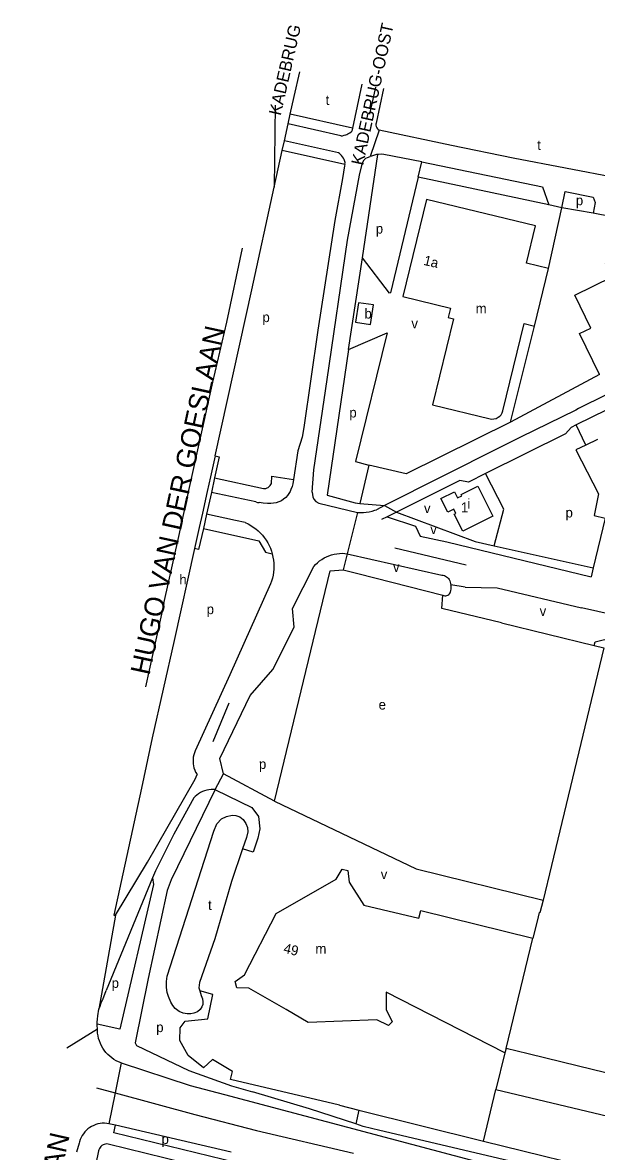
# Model space of a CAD drawing. Extents: x 162804 to 165059, y 381530 to 382901.
# Drawn here: x 163020.7 to 163254, y 382442.3 to 382900.9 of the extents above; entities that cross this region are included whole.
import ezdxf

# ---------------------------------------------------------------- set-up
doc = ezdxf.new("R2010")
doc.units = 0
for name, color, linetype in [('BLT_Basislijn', 7, 'Continuous'), ('BLT_Bebouwing', 7, 'Continuous'), ('BLT_Centroide', 7, 'Continuous'), ('BLT_Huisnummer', 7, 'Continuous'), ('BLT_Onderverdeling_panden', 7, 'Continuous'), ('BLT_Straatnaam', 7, 'Continuous'), ('BLT_Straatnaam_hoofdweg', 7, 'Continuous'), ('BLT_Vlakafsluiter', 7, 'Continuous')]:
    doc.layers.add(name, color=color, linetype=linetype)

msp = doc.modelspace()

# ---------------------------------------------------------------- linework, layer by layer
at = {"layer": 'BLT_Basislijn'}
for p, q in [((163131.06, 382870.79), (163133.35, 382880.87)), ((163158.64, 382875.8), (163154.76, 382858.01)), ((163164.16, 382874.7), (163161.76, 382863.69)), ((163167.47, 382874.04), (163164.41, 382860.02)), ((163129.49, 382863.62), (163131.06, 382870.79)), ((163127.14, 382852.84), (163128.64, 382859.71)), ((163128.64, 382859.71), (163129.49, 382863.62)), ((163154.76, 382858.01), (163154.5, 382856.8)), ((163195.06, 382850.97), (163165.62, 382857.21)), ((163126.28, 382848.93), (163127.14, 382852.84)), ((163123.04, 382834.08), (163126.28, 382848.93)), ((163181.57, 382838.06), (163183.05, 382844.29)), ((163234.54, 382800.98), (163240, 382825.68)), ((163153.25, 382768.15), (163158.84, 382805.26)), ((163219.01, 382738.59), (163228.81, 382777.5)), ((163299.49, 382763.84), (163245.82, 382737.43)), ((163255.22, 382757.98), (163219.01, 382738.59)), ((163249.72, 382729.24), (163245.82, 382737.43)), ((163214.74, 382728.24), (163167.81, 382704.66)), ((163098.97, 382724.93), (163097.07, 382716.36)), ((163097.07, 382716.36), (163095.75, 382710.42)), ((163098.78, 382715.98), (163097.47, 382710.05)), ((163098.78, 382715.98), (163118.59, 382711.58)), ((163121.92, 382713.69), (163122.04, 382716.59)), ((163122.04, 382716.59), (163130.81, 382715.3)), ((163095.75, 382710.42), (163093.8, 382701.6)), ((163097.47, 382710.05), (163095.52, 382701.22)), ((163115.46, 382706.15), (163097.47, 382710.05)), ((163157.82, 382705.56), (163167.81, 382704.66)), ((163167.81, 382704.66), (163164.52, 382703)), ((163093.8, 382701.6), (163092.51, 382695.79)), ((163095.52, 382701.22), (163094.24, 382695.41)), ((163156.91, 382701.93), (163152.71, 382685.13)), ((163168.89, 382700.14), (163166.62, 382699.01)), ((163172.66, 382702.02), (163168.89, 382700.14)), ((163092.51, 382695.79), (163090.61, 382687.21)), ((163090.61, 382687.21), (163082.34, 382649.92)), ((163172.04, 382687.5), (163201.03, 382680.57)), ((163212.49, 382688.33), (163252.69, 382679.34)), ((163152.71, 382685.13), (163191.18, 382676.38)), ((163252.69, 382679.34), (163251.83, 382675.68)), ((163121.51, 382672.9), (163104.93, 382635.89)), ((163194.35, 382674.13), (163194.79, 382672.55)), ((163078.08, 382664.93), (163070.68, 382631.05)), ((163215.41, 382657.03), (163253.08, 382647.9)), ((163253.08, 382647.9), (163257.08, 382646.93)), ((163104.93, 382635.89), (163090.89, 382605.04)), ((163104.57, 382624.4), (163098.01, 382608.72)), ((163098.98, 382589.29), (163102.38, 382595.76)), ((163099.17, 382589.28), (163098.98, 382589.29)), ((163099.17, 382589.28), (163113.86, 382582.1)), ((163073.55, 382553.53), (163054.64, 382507.76)), ((163053.27, 382504.11), (163054.64, 382507.76)), ((163216.75, 382482.33), (163213.07, 382467.42)), ((163102.84, 382465.46), (163245.33, 382427.71)), ((163208.07, 382446.49), (163213.07, 382467.42)), ((163213.07, 382467.42), (163350, 382434.88)), ((163149.58, 382461.08), (163157.34, 382459.15)), ((163157.34, 382459.15), (163156.24, 382453.48)), ((163157.34, 382459.15), (163208.07, 382446.49)), ((163058.49, 382452.93), (163055.79, 382453.57)), ((163057.73, 382449.9), (163058.49, 382452.93)), ((163105.48, 382442), (163058.49, 382452.93)), ((163113.31, 382436.31), (163057.73, 382449.9)), ((163051.6, 382442.55), (163036.49, 382372.02)), ((163043.68, 382445.63), (163042.61, 382441.97)), ((163115.9, 382430.53), (163055.43, 382445.32)), ((163208.07, 382446.49), (163350, 382411.77))]:
    msp.add_line(p, q, dxfattribs=at)
for points in [[(163150.12, 382854.94), (163128.64, 382859.71)], [(163154.76, 382858.01), (163129.49, 382863.62)], [(163164.41, 382860.02), (163164.37, 382859.62), (163164.37, 382859.16), (163164.47, 382858.65), (163164.69, 382858.12), (163164.94, 382857.77), (163165.23, 382857.5), (163165.62, 382857.21)], [(163150.12, 382854.94), (163150.8, 382854.93), (163151.41, 382855.09), (163152.08, 382855.28), (163152.55, 382855.46), (163152.95, 382855.64), (163153.69, 382856.11), (163154.29, 382856.51), (163154.5, 382856.8)], [(163149.07, 382847.94), (163127.14, 382852.84)], [(163262.7, 382837.7), (163220.15, 382845.79), (163195.06, 382850.97)], [(163151.69, 382843.25), (163126.28, 382848.93)], [(163138.38, 382710.09), (163139.04, 382719.2), (163144.49, 382755.86), (163152.81, 382812.54), (163157.67, 382838.95), (163158.87, 382843.86), (163159.61, 382845.11), (163160.28, 382845.75), (163160.93, 382846.09), (163162.05, 382846.43)], [(163151.68, 382843.24), (163151.8, 382844.07), (163151.74, 382844.42), (163151.57, 382844.89), (163151.39, 382845.22), (163151.11, 382845.76), (163150.78, 382846.28), (163150.31, 382846.88), (163149.79, 382847.48), (163149.52, 382847.71), (163149.07, 382847.94)], [(163158.84, 382805.26), (163165.1, 382847.3)], [(163165.1, 382847.3), (163164.58, 382847.23), (163163.4, 382846.94), (163162.6, 382846.66), (163162.05, 382846.43)], [(163183.05, 382844.29), (163167.53, 382847.36), (163166.55, 382847.41), (163165.44, 382847.35), (163165.1, 382847.3)], [(163151.68, 382843.24), (163151.64, 382842.74), (163150.73, 382837.51), (163147.6, 382820.47), (163140.79, 382775.98), (163134.99, 382736.38), (163134.35, 382732.42), (163132.58, 382726.92), (163130.81, 382715.3)], [(163183.05, 382844.29), (163232.1, 382834.21), (163234.59, 382826.79)], [(163181.57, 382838.06), (163170.28, 382791.11), (163169.86, 382790.92), (163158.84, 382805.26)], [(163234.59, 382826.79), (163181.57, 382838.06)], [(163098.97, 382724.93), (163113.91, 382792.3), (163123.04, 382834.08)], [(163240, 382825.68), (163241.32, 382832.3), (163252.7, 382829.96), (163253.56, 382827.74), (163252.7, 382823.52)], [(163240, 382825.68), (163234.59, 382826.79)], [(163252.7, 382823.52), (163240, 382825.68)], [(163260.28, 382821.96), (163252.7, 382823.52)], [(163098.1, 382754.82), (163103.69, 382779.15), (163110.05, 382809.31)], [(163342.88, 382788.54), (163334.37, 382786.16), (163324.71, 382782.9), (163300, 382770.11), (163280.94, 382760.98), (163246.71, 382744.11), (163245.68, 382743.43), (163223.18, 382732.48), (163214.74, 382728.24)], [(163153.25, 382768.15), (163168.88, 382774.85), (163156.04, 382722.53), (163161.49, 382721.16)], [(163153.25, 382768.15), (163144.56, 382708.96), (163155.87, 382705.74), (163157.82, 382705.56)], [(163088.58, 382711.97), (163098.1, 382754.82)], [(163219.01, 382738.59), (163176.6, 382717.59), (163161.49, 382721.16)], [(163245.82, 382737.43), (163243.69, 382736.38), (163241.47, 382733.8), (163208.95, 382717.76)], [(163254.47, 382731.57), (163249.72, 382729.24)], [(163249.72, 382729.24), (163245.69, 382727.26), (163254.86, 382709.41), (163253.04, 382700.65), (163257.5, 382699.61), (163252.69, 382679.34)], [(163098.97, 382724.93), (163100.68, 382724.55), (163098.78, 382715.98)], [(163161.49, 382721.16), (163157.82, 382705.56)], [(163208.95, 382717.76), (163201.99, 382714.15), (163198.52, 382714.88), (163172.66, 382702.02)], [(163212.49, 382688.33), (163216.34, 382703.16), (163208.95, 382717.76)], [(163130.81, 382715.3), (163130.54, 382713.58), (163130.26, 382712.47), (163129.8, 382711.16), (163129.48, 382710.42), (163128.95, 382709.53), (163128.36, 382708.74), (163127.69, 382707.98), (163126.82, 382707.25), (163125.9, 382706.65), (163124.86, 382706.17), (163123.8, 382705.84), (163122.68, 382705.61), (163121.57, 382705.5), (163120.21, 382705.48), (163118.51, 382705.68), (163116.94, 382705.89)], [(163118.59, 382711.58), (163119.11, 382711.59), (163119.62, 382711.68), (163120.11, 382711.85), (163120.57, 382712.09), (163120.99, 382712.4), (163121.36, 382712.77), (163121.66, 382713.19), (163121.92, 382713.69)], [(163078.08, 382664.93), (163084.25, 382692.16), (163088.58, 382711.97)], [(163138.38, 382710.09), (163138.64, 382708.3), (163139.1, 382707.22), (163139.9, 382706.36), (163141.09, 382705.65), (163156.91, 382701.93)], [(163115.46, 382706.15), (163116.24, 382705.97), (163116.94, 382705.89)], [(163111.24, 382697.77), (163107.3, 382698.6), (163095.52, 382701.22)], [(163156.91, 382701.93), (163158.09, 382701.88), (163159.27, 382701.9), (163160.45, 382702), (163161.62, 382702.18), (163162.77, 382702.44), (163163.9, 382702.78), (163164.52, 382703)], [(163168.89, 382700.14), (163180.47, 382696.27), (163182.3, 382692.26), (163193.24, 382689.89), (163251.83, 382675.68)], [(163172.66, 382702.02), (163204.72, 382690.07), (163212.49, 382688.33)], [(163094.24, 382695.41), (163092.16, 382686.86), (163090.61, 382687.21)], [(163094.24, 382695.41), (163116.78, 382690.4), (163119.41, 382685.76), (163122.2, 382685.07)], [(163111.24, 382697.77), (163112.36, 382697.24), (163113.45, 382696.63), (163114.49, 382695.96), (163115.5, 382695.22), (163116.45, 382694.42), (163117.35, 382693.56), (163118.19, 382692.64), (163118.97, 382691.67), (163119.68, 382690.65), (163120.34, 382689.59), (163120.92, 382688.49), (163121.42, 382687.36), (163121.86, 382686.19), (163122.2, 382685.07)], [(163139.08, 382679.93), (163139.81, 382680.74), (163140.6, 382681.49), (163141.44, 382682.19), (163142.33, 382682.83), (163143.26, 382683.4), (163144.23, 382683.89), (163145.24, 382684.32), (163146.27, 382684.67), (163147.33, 382684.94), (163148.4, 382685.14), (163149.49, 382685.26), (163150.58, 382685.29), (163151.67, 382685.25), (163152.71, 382685.13)], [(163122.2, 382685.07), (163122.5, 382683.79), (163122.7, 382682.56), (163122.83, 382681.32), (163122.87, 382680.08), (163122.83, 382678.83), (163122.72, 382677.59), (163122.52, 382676.36), (163122.25, 382675.15), (163121.9, 382673.96), (163121.51, 382672.9)], [(163152.71, 382685.13), (163151.07, 382678.57)], [(163102.38, 382595.76), (163100.86, 382601.96), (163113.25, 382627.5), (163122.37, 382638.08), (163131.12, 382655.23), (163130.39, 382662.89), (163139.08, 382679.93)], [(163123.14, 382584.58), (163145.77, 382678.15), (163151.07, 382678.57)], [(163151.07, 382678.57), (163157.03, 382677.05)], [(163157.03, 382677.05), (163191.57, 382668.27)], [(163191.18, 382676.38), (163191.69, 382676.35), (163192.19, 382676.24), (163192.67, 382676.05), (163193.11, 382675.79), (163193.51, 382675.47), (163193.85, 382675.09), (163194.12, 382674.66), (163194.35, 382674.13)], [(163194.69, 382669.54), (163194.86, 382670.15), (163194.96, 382670.78), (163194.97, 382671.41), (163194.9, 382672.04), (163194.79, 382672.55)], [(163200.64, 382671.5), (163213.64, 382671.33), (163247.91, 382663.13)], [(163215.41, 382657.03), (163191.12, 382662.93), (163191.57, 382668.27)], [(163191.57, 382668.27), (163191.98, 382668.13), (163192.4, 382668.06), (163192.83, 382668.07), (163193.24, 382668.16), (163193.64, 382668.33), (163193.99, 382668.57), (163194.3, 382668.87), (163194.54, 382669.22), (163194.69, 382669.54)], [(163082.34, 382649.92), (163073.42, 382610.36), (163069.04, 382589.94)], [(163253.08, 382647.9), (163253.44, 382649.38), (163267.8, 382652.86), (163288.01, 382648.03)], [(163090.89, 382605.04), (163090.56, 382604.22), (163090.29, 382603.37), (163090.11, 382602.5), (163090.01, 382601.61), (163089.98, 382600.73), (163090.04, 382599.84), (163090.17, 382598.96), (163090.38, 382598.09), (163090.67, 382597.25), (163091.04, 382596.44), (163091.47, 382595.67), (163091.64, 382595.41)], [(163058.48, 382538.35), (163071.41, 382559.86), (163090.91, 382593.59), (163091.64, 382595.41)], [(163123.14, 382584.58), (163102.38, 382595.76)], [(163069.04, 382589.94), (163057.75, 382538.35), (163058.48, 382538.35)], [(163098.98, 382589.29), (163081.08, 382552.64), (163079.44, 382548.27), (163071.78, 382512.54)], [(163098.98, 382589.29), (163098.26, 382589.35), (163097.35, 382589.34), (163096.45, 382589.24), (163095.56, 382589.08), (163094.68, 382588.83), (163093.84, 382588.5), (163093.02, 382588.11), (163092.24, 382587.64), (163091.51, 382587.11), (163090.82, 382586.51), (163090.33, 382586.01)], [(163090.33, 382586.01), (163082.16, 382571.22), (163074.69, 382556.27), (163073.55, 382553.53)], [(163123.14, 382584.58), (163180.65, 382557.11), (163232.29, 382544.44)], [(163113.86, 382582.1), (163116.57, 382578.36), (163117.21, 382573.31), (163116.3, 382569.58), (163114.44, 382563.9), (163110.13, 382565.26)], [(163093.85, 382504.27), (163094.01, 382503.13), (163093.92, 382501.98), (163093.59, 382501.07), (163092.92, 382499.98), (163091.86, 382499.09), (163090.29, 382498.44), (163089.05, 382498.21), (163087.56, 382498.19), (163085.99, 382498.48), (163084.36, 382499.19), (163082.78, 382500.34), (163081.72, 382501.54), (163080.95, 382502.95), (163079.99, 382505.25), (163079.51, 382506.94), (163079.19, 382508.95), (163079.15, 382511.36), (163079.41, 382513.58), (163098.44, 382572.38), (163099.71, 382575.41), (163101.56, 382577.37), (163103.57, 382578.44), (163105.84, 382578.95), (163107.42, 382578.83), (163108.96, 382578.2), (163110.35, 382577.16), (163111.49, 382575.57), (163112.1, 382573.95), (163112.26, 382572.18), (163111.67, 382569.8), (163110.13, 382565.26)], [(163110.13, 382565.26), (163105.63, 382551.99), (163098.86, 382528.65), (163092.62, 382510.96), (163092.42, 382509.84), (163092.37, 382508.78), (163092.7, 382507.58)], [(163073.55, 382553.53), (163073.88, 382550.7), (163060.21, 382491.97), (163051, 382494.09)], [(163071.78, 382512.54), (163066.4, 382486.49), (163066.95, 382485.4), (163088.28, 382475.18), (163105.6, 382468.98), (163114.23, 382466.55)], [(163106.08, 382474.74), (163097.94, 382479.7), (163094.25, 382476.24), (163088.02, 382481.28), (163084.63, 382487.43), (163084.81, 382492.48), (163086.74, 382495.23), (163095.99, 382496.15), (163098.03, 382506.14), (163092.7, 382507.58)], [(163092.7, 382507.58), (163093.23, 382505.63), (163093.85, 382504.27)], [(163051.69, 382500.12), (163052.17, 382501.4), (163052.63, 382502.66), (163053.17, 382503.9), (163053.27, 382504.11)], [(163051, 382494.09), (163051, 382494.78), (163051.08, 382496.12), (163051.23, 382497.46), (163051.69, 382500.12)], [(163051.08, 382492.14), (163051, 382493.43), (163051, 382494.09)], [(163051.09, 382492.08), (163051.08, 382492.14)], [(163060.75, 382478.28), (163059.75, 382478.69), (163058.78, 382479.17), (163057.85, 382479.72), (163056.96, 382480.33), (163056.11, 382481.01), (163055.32, 382481.75), (163054.59, 382482.55), (163053.92, 382483.4), (163053.31, 382484.29), (163052.77, 382485.23), (163052.31, 382486.21), (163051.91, 382487.22), (163051.59, 382488.25), (163051.35, 382489.3), (163051.18, 382490.37), (163051.1, 382491.45), (163051.09, 382492.08)], [(163060.75, 382478.28), (163088.81, 382469.1), (163102.84, 382465.46)], [(163149.58, 382461.08), (163105.23, 382471.59), (163106.08, 382474.74)], [(163050.77, 382468.16), (163058.31, 382466.11)], [(163058.31, 382466.11), (163090.7, 382457.32), (163115.81, 382450.81), (163155.19, 382441.59)], [(163156.24, 382453.48), (163137.37, 382459.62), (163114.23, 382466.55)], [(163055.79, 382453.57), (163054.9, 382453.71), (163053.99, 382453.77), (163053.09, 382453.76), (163052.19, 382453.66), (163051.3, 382453.49), (163050.43, 382453.23), (163049.59, 382452.9), (163048.77, 382452.5), (163048, 382452.03), (163047.27, 382451.49), (163046.59, 382450.89), (163045.97, 382450.24), (163045.41, 382449.53), (163044.91, 382448.77), (163044.48, 382447.97), (163044.12, 382447.14), (163043.84, 382446.28), (163043.68, 382445.63)], [(163250.71, 382430.99), (163165.98, 382450.87), (163159.23, 382452.51), (163156.24, 382453.48)], [(163055.43, 382445.32), (163054.9, 382445.35), (163054.38, 382445.3), (163053.87, 382445.17), (163053.39, 382444.96), (163052.95, 382444.68), (163052.55, 382444.34), (163052.21, 382443.94), (163051.93, 382443.5), (163051.73, 382443.02), (163051.6, 382442.55)]]:
    msp.add_lwpolyline(points, dxfattribs=at)
at = {"layer": 'BLT_Bebouwing'}
for p, q in [((163228.81, 382777.5), (163234.54, 382800.98)), ((163190.8, 382707.52), (163196.32, 382710.24)), ((163235.68, 382558.47), (163232.29, 382544.44)), ((163229.89, 382535.9), (163228.21, 382528.97)), ((163216.75, 382482.33), (163168.52, 382507.07)), ((163217.26, 382484.11), (163216.75, 382482.33))]:
    msp.add_line(p, q, dxfattribs=at)
for points in [[(163234.54, 382800.98), (163225.61, 382803.16), (163229.29, 382818.25), (163184.93, 382829.07), (163175.29, 382789.56), (163194.64, 382784.88), (163193.71, 382781.12), (163195.86, 382780.59), (163187.29, 382745.55), (163210.74, 382739.91), (163211.35, 382739.83), (163212.24, 382739.87), (163213.2, 382740.11), (163214.02, 382740.53), (163214.68, 382741.02), (163215.21, 382741.58), (163215.68, 382742.3), (163216.01, 382743.2), (163224.63, 382778.58), (163228.81, 382777.5)], [(163255.22, 382757.98), (163247.16, 382774.53), (163251.74, 382776.76), (163245.19, 382790.18), (163260.38, 382797.59), (163257.72, 382803.04), (163272.56, 382810.28), (163275.22, 382804.83), (163285.92, 382810.05), (163300.53, 382780.1)], [(163162.18, 382778.25), (163163.39, 382786.17), (163157.2, 382787.07), (163156, 382779.19), (163162.18, 382778.25)], [(163196.32, 382710.24), (163197.53, 382707.78), (163199.24, 382708.63), (163198.95, 382709.22), (163205.82, 382712.62), (163211.85, 382700.39), (163199.63, 382694.34), (163196.2, 382701.21), (163196.83, 382701.53), (163196.01, 382703.25), (163193.55, 382702.02), (163190.8, 382707.52)], [(163257.08, 382646.93), (163235.68, 382558.47)], [(163168.52, 382507.07), (163168.5, 382500), (163170.9, 382494.92), (163169.52, 382493.45), (163164.72, 382495.81), (163136.83, 382494.76), (163127.88, 382500), (163112.66, 382508.61), (163107.74, 382508.81), (163107.08, 382511.39), (163110.95, 382514.11), (163123.85, 382538.93), (163148.21, 382552.88), (163150.66, 382556.93), (163152.9, 382556.47), (163153.47, 382551.73), (163159.39, 382542.43)], [(163232.29, 382544.44), (163231.05, 382539.31), (163230.73, 382539.39), (163229.89, 382535.9)], [(163159.39, 382542.43), (163181.78, 382537.03), (163182.56, 382540.25), (163228.21, 382528.97)], [(163226.29, 382481.93), (163217.26, 382484.11)], [(163246.71, 382476.98), (163226.29, 382481.93)], [(163288.5, 382466.86), (163246.71, 382476.98)]]:
    msp.add_lwpolyline(points, dxfattribs=at)
at = {"layer": 'BLT_Onderverdeling_panden'}
msp.add_line((163217.26, 382484.11), (163228.21, 382528.97), dxfattribs=at)
at = {"layer": 'BLT_Vlakafsluiter'}
for p, q in [((163123.37, 382867.27), (163123.04, 382834.08)), ((163165.62, 382857.21), (163162.05, 382846.43)), ((163167.81, 382704.66), (163172.66, 382702.02)), ((163200.64, 382671.5), (163194.79, 382672.55)), ((163058.48, 382538.35), (163051.69, 382500.12)), ((163038.65, 382484.4), (163051.09, 382492.08)), ((163038.66, 382484.46), (163051.08, 382492.14)), ((163060.75, 382478.28), (163058.31, 382466.11)), ((163058.31, 382466.11), (163055.79, 382453.57))]:
    msp.add_line(p, q, dxfattribs=at)
msp.add_lwpolyline([(163288.01, 382648.03), (163283.58, 382655.2), (163247.91, 382663.13)], dxfattribs=at)

# ---------------------------------------------------------------- texts
at = {"layer": 'BLT_Centroide'}
for s, p in [('t', (163143.91, 382867.41)), ('t', (163229.94, 382849.15)), ('p', (163245.65, 382826.7)), ('p', (163164.3, 382815.17)), ('p', (163118.21, 382779.22)), ('b', (163159.69, 382780.67)), ('m', (163204.91, 382782.75)), ('v', (163178.76, 382776.66)), ('p', (163153.55, 382740.48)), ('v', (163183.9, 382701.64)), ('i', (163201.57, 382703.47)), ('p', (163241.45, 382699.84)), ('v', (163186.45, 382693.07)), ('v', (163171.29, 382677.74)), ('h', (163084.43, 382672.63)), ('p', (163095.53, 382660.59)), ('v', (163230.92, 382659.84)), ('e', (163165.45, 382621.83)), ('p', (163116.79, 382597.67)), ('v', (163166.31, 382552.93)), ('t', (163096.08, 382540.38)), ('m', (163139.75, 382522.71)), ('p', (163056.9, 382508.76)), ('p', (163075.02, 382490.8)), ('p', (163077.18, 382445.38))]:
    msp.add_text(s, height=4, dxfattribs=at).set_placement(p)
at = {"layer": 'BLT_Huisnummer'}
for s, rotation, p in [('1a', 346.6283, (163183.48, 382802.51)), ('49', 346.779, (163126.52, 382523.07))]:
    msp.add_text(s, height=4, rotation=rotation, dxfattribs=at).set_placement(p)
msp.add_text('1', height=4, dxfattribs=at).set_placement((163198.89, 382701.96))
at = {"layer": 'BLT_Straatnaam'}
for s, rotation, p in [('KADEBRUG-OOST', 77.6985, (163159.12, 382842.62)), ('KADEBRUG', 77.1889, (163125.61, 382862.86))]:
    msp.add_text(s, height=5, rotation=rotation, dxfattribs=at).set_placement(p)
at = {"layer": 'BLT_Straatnaam_hoofdweg'}
for s, rotation, p in [('HUGO VAN DER GOESLAAN', 77.7518, (163072.28, 382635.48)), ('PIUSLAAN', 77.342, (163028.29, 382397.24))]:
    msp.add_text(s, height=8, rotation=rotation, dxfattribs=at).set_placement(p)

doc.saveas('drawing.dxf')
